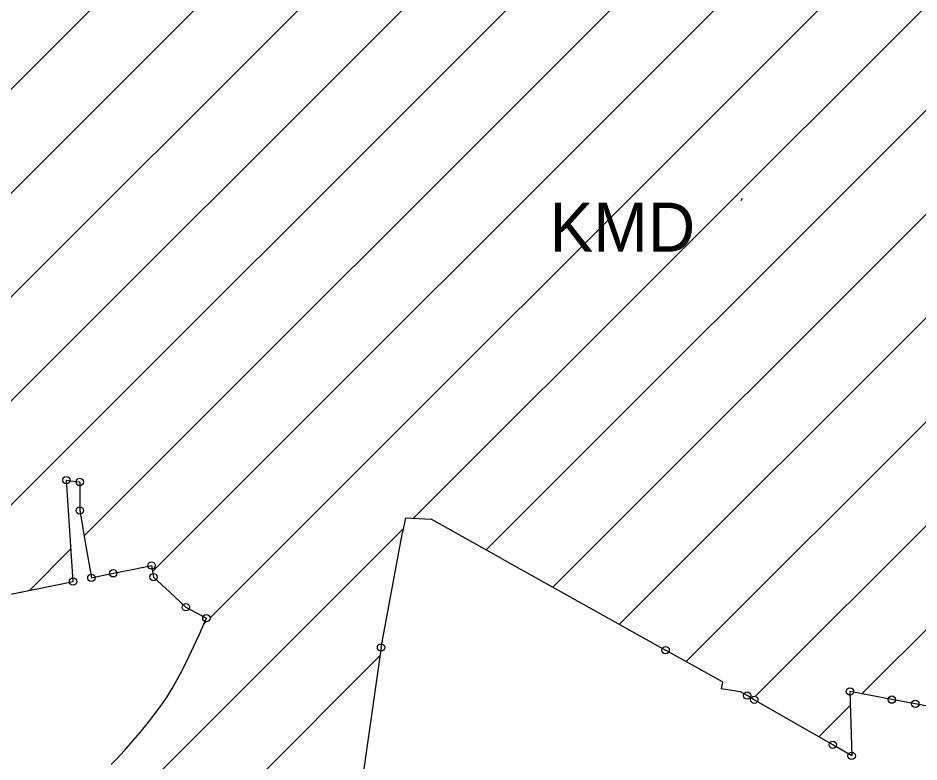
# Model space of a CAD drawing. Extents: x -623137 to -616791, y -1192758 to -1186540.
# Drawn here: x -618627.9 to -618260.3, y -1189490.9 to -1189187.2 of the extents above; entities that cross this region are included whole.
import ezdxf

# ---------------------------------------------------------------- set-up
doc = ezdxf.new("R2010")
doc.units = 0
for name, color, linetype in [('Legenda', 7, 'Continuous'), ('Pop_ PČ_ popisy', 7, 'Continuous'), ('Vrstva 13', 7, 'Continuous'), ('Vrstva 59', 7, 'Continuous'), ('Vzdy červené', 7, 'Continuous')]:
    doc.layers.add(name, color=color, linetype=linetype)

msp = doc.modelspace()

# ---------------------------------------------------------------- linework, layer by layer
at = {"layer": 'Legenda'}
for p, q in [((-618768.66, -1189354.16), (-618441.66, -1189027.16)), ((-618726.58, -1189354.51), (-618415.39, -1189043.32)), ((-618684.77, -1189355.12), (-618382.56, -1189052.92)), ((-618641.76, -1189354.54), (-618343.69, -1189056.47)), ((-618549.52, -1189432), (-618201.17, -1189083.65)), ((-618638.82, -1189394.02), (-618339.17, -1189094.37)), ((-618466.46, -1189391.37), (-618167.33, -1189092.25)), ((-618436.92, -1189404.26), (-618131.96, -1189099.3)), ((-618600.9, -1189398.53), (-618309.27, -1189106.9)), ((-618409.7, -1189419.46), (-618097.36, -1189107.12)), ((-618382.48, -1189434.67), (-618062.76, -1189114.95)), ((-618573.01, -1189413.07), (-618281.02, -1189121.08)), ((-618355.26, -1189449.88), (-618058.35, -1189152.97)), ((-618327, -1189464.04), (-618029.54, -1189166.59)), ((-618283.6, -1189463.07), (-618012.46, -1189191.93)), ((-618654.47, -1189579.38), (-618470.64, -1189395.56)), ((-618623.18, -1189420.82), (-618606.29, -1189403.92)), ((-618552.06, -1189434.55), (-618551.18, -1189433.66)), ((-618627.3, -1189594.64), (-618480.26, -1189447.6)), ((-618301.15, -1189480.62), (-618288.31, -1189467.78))]:
    msp.add_line(p, q, dxfattribs=at)
at = {"layer": 'Pop_ PČ_ popisy'}
msp.add_lwpolyline([(-618332.81, -1189261.67), (-618332.33, -1189260.77)], dxfattribs=at)
at = {"layer": 'Vrstva 13'}
for p, q in [((-618606.78, -1189396.51), (-618608.13, -1189375.82)), ((-618608.13, -1189375.82), (-618605.4, -1189376.2)), ((-618605.4, -1189376.2), (-618602.67, -1189376.58)), ((-618602.67, -1189376.58), (-618602.68, -1189382.41)), ((-618602.68, -1189382.41), (-618602.68, -1189388.23)), ((-618602.68, -1189388.23), (-618600.31, -1189401.96)), ((-618469.82, -1189391.19), (-618470.96, -1189397.23)), ((-618469.82, -1189391.19), (-618459.3, -1189391.76)), ((-618430.63, -1189407.77), (-618459.3, -1189391.76)), ((-618605.42, -1189417.2), (-618606.78, -1189396.51)), ((-618479.76, -1189444.11), (-618470.96, -1189397.23)), ((-618470.96, -1189397.23), (-618470.96, -1189397.23)), ((-618600.31, -1189401.96), (-618597.93, -1189415.68)), ((-618430.63, -1189407.77), (-618363.66, -1189445.19)), ((-618581.22, -1189412.28), (-618573.44, -1189410.7)), ((-618573.44, -1189410.7), (-618572.58, -1189415.39)), ((-618597.93, -1189415.68), (-618593.46, -1189414.77)), ((-618593.46, -1189414.77), (-618589, -1189413.86)), ((-618589, -1189413.86), (-618581.22, -1189412.28)), ((-618620.7, -1189420.31), (-618605.42, -1189417.2)), ((-618572.58, -1189415.39), (-618565.98, -1189421.53)), ((-618648.5, -1189425.97), (-618620.7, -1189420.31)), ((-618565.98, -1189421.53), (-618559.39, -1189427.66)), ((-618559.39, -1189427.66), (-618551.01, -1189432.17)), ((-618479.76, -1189444.11), (-618489.91, -1189515.27)), ((-618479.76, -1189444.11), (-618479.76, -1189444.11)), ((-618479.76, -1189444.11), (-618479.76, -1189444.11)), ((-618340.49, -1189458.14), (-618363.66, -1189445.19)), ((-618363.66, -1189445.19), (-618363.66, -1189445.19)), ((-618363.66, -1189445.19), (-618363.66, -1189445.19)), ((-618340.49, -1189458.14), (-618340.94, -1189461.08)), ((-618333.07, -1189462.29), (-618340.94, -1189461.08)), ((-618330.4, -1189463.78), (-618333.07, -1189462.29)), ((-618271.35, -1189465.42), (-618288.46, -1189462.14)), ((-618288.46, -1189462.14), (-618287.76, -1189488.33)), ((-618327.48, -1189465.46), (-618330.4, -1189463.78)), ((-618295.49, -1189483.88), (-618327.48, -1189465.46)), ((-618261.8, -1189467.12), (-618271.35, -1189465.42)), ((-618242.14, -1189470.79), (-618261.8, -1189467.12)), ((-618287.76, -1189488.33), (-618295.49, -1189483.88))]:
    msp.add_line(p, q, dxfattribs=at)
at = {"layer": 'Vrstva 59'}
for p, q in [((-618554, -1189438.92), (-618551.01, -1189432.17)), ((-618559.3, -1189450.23), (-618554, -1189438.92)), ((-618561.54, -1189454.71), (-618559.3, -1189450.23)), ((-618564.91, -1189460.85), (-618561.54, -1189454.71)), ((-618566.96, -1189464.26), (-618564.91, -1189460.85)), ((-618564.91, -1189460.85), (-618564.91, -1189460.85)), ((-618569.84, -1189468.35), (-618566.96, -1189464.26)), ((-618574.66, -1189474.67), (-618569.84, -1189468.35)), ((-618578.01, -1189478.84), (-618574.66, -1189474.67)), ((-618584.43, -1189486.16), (-618578.01, -1189478.84)), ((-618587.77, -1189489.8), (-618584.43, -1189486.16)), ((-618589.91, -1189491.92), (-618587.77, -1189489.8))]:
    msp.add_line(p, q, dxfattribs=at)
at = {"layer": 'Vzdy červené'}
for centre in [(-618608.13, -1189375.82), (-618602.67, -1189376.58), (-618602.68, -1189388.23), (-618573.44, -1189410.7), (-618597.93, -1189415.68), (-618589, -1189413.86), (-618572.58, -1189415.39), (-618605.42, -1189417.2), (-618559.39, -1189427.66), (-618551.01, -1189432.17), (-618479.76, -1189444.11), (-618363.66, -1189445.19), (-618330.4, -1189463.78), (-618288.46, -1189462.14), (-618327.48, -1189465.46), (-618271.35, -1189465.42), (-618261.8, -1189467.12), (-618295.49, -1189483.88), (-618287.76, -1189488.33)]:
    msp.add_circle(centre, 1.5, dxfattribs=at)

# ---------------------------------------------------------------- texts
msp.add_text('KMD', height=20, dxfattribs=at).set_placement((-618411.04, -1189282.56))

doc.saveas('drawing.dxf')
